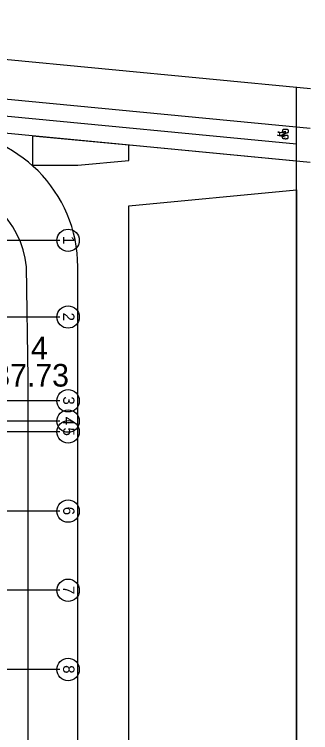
# Model space of a CAD drawing. Extents: x -264165 to -263575, y -1242333 to -1242036.
# Drawn here: x -263791.5 to -263765.3, y -1242131.5 to -1242068 of the extents above; entities that cross this region are included whole.
import ezdxf

# ---------------------------------------------------------------- set-up
doc = ezdxf.new("R2010")
doc.units = 0
for name, color, linetype in [('KFA_BODY_VYTYCOVAK', 7, 'Continuous'), ('KFA_HESCON_OSI_STAVBY', 7, 'Continuous'), ('KFA_SITUACIA_DRS_VYTYCOVAK_SEDA', 7, 'Continuous')]:
    doc.layers.add(name, color=color, linetype=linetype)

msp = doc.modelspace()

# ---------------------------------------------------------------- linework, layer by layer
at = {"layer": 'KFA_HESCON_OSI_STAVBY'}
for p, q in [((-263787.486, -1242087.957), (-263921.823, -1242087.957)), ((-263787.486, -1242087.957), (-263787.486, -1242087.957)), ((-263787.486, -1242094.732), (-263921.823, -1242094.732)), ((-263787.486, -1242094.732), (-263787.486, -1242094.732)), ((-263787.486, -1242102.132), (-263921.823, -1242102.132)), ((-263787.486, -1242102.132), (-263787.486, -1242102.132)), ((-263787.486, -1242103.932), (-263921.823, -1242103.932)), ((-263787.486, -1242103.932), (-263787.486, -1242103.932)), ((-263787.486, -1242104.882), (-263921.823, -1242104.882)), ((-263787.486, -1242104.882), (-263787.486, -1242104.882)), ((-263787.486, -1242111.882), (-263921.823, -1242111.882)), ((-263787.486, -1242111.882), (-263787.486, -1242111.882)), ((-263787.486, -1242118.882), (-263921.823, -1242118.882)), ((-263787.486, -1242118.882), (-263787.486, -1242118.882)), ((-263787.486, -1242125.882), (-263921.823, -1242125.882)), ((-263787.486, -1242125.882), (-263787.486, -1242125.882))]:
    msp.add_line(p, q, dxfattribs=at)
for centre in [(-263786.751, -1242087.956), (-263786.751, -1242094.731), (-263786.751, -1242102.131), (-263786.751, -1242103.931), (-263786.751, -1242104.881), (-263786.751, -1242111.881), (-263786.751, -1242118.881), (-263786.751, -1242125.881)]:
    msp.add_circle(centre, 0.991, dxfattribs=at)
at = {"layer": 'KFA_SITUACIA_DRS_VYTYCOVAK_SEDA'}
for p, q in [((-263765.318, -1242074.565), (-263863.949, -1242065.106)), ((-263765.364, -1242078.076), (-263864.283, -1242068.59)), ((-263766.58, -1242079.467), (-263864.426, -1242070.084)), ((-263765.366, -1242081.09), (-263864.57, -1242071.577)), ((-263766.58, -1242080.973), (-263864.546, -1242071.579)), ((-263766.58, -1242144.85), (-263766.58, -1242074.389)), ((-263768.17, -1242078.443), (-263768.167, -1242078.342)), ((-263768.037, -1242078.422), (-263768.168, -1242078.393)), ((-263768.046, -1242078.721), (-263768.037, -1242078.422)), ((-263768.037, -1242078.422), (-263767.545, -1242078.308)), ((-263767.552, -1242078.528), (-263768.037, -1242078.422)), ((-263767.811, -1242078.279), (-263767.812, -1242078.312)), ((-263767.812, -1242078.312), (-263767.812, -1242078.333)), ((-263767.812, -1242078.333), (-263767.811, -1242078.349)), ((-263767.809, -1242078.257), (-263767.811, -1242078.279)), ((-263767.811, -1242078.349), (-263767.808, -1242078.363)), ((-263767.806, -1242078.239), (-263767.809, -1242078.257)), ((-263767.808, -1242078.363), (-263767.803, -1242078.375)), ((-263767.801, -1242078.223), (-263767.806, -1242078.239)), ((-263767.803, -1242078.375), (-263767.796, -1242078.387)), ((-263767.795, -1242078.209), (-263767.801, -1242078.223)), ((-263767.796, -1242078.387), (-263767.787, -1242078.398)), ((-263767.786, -1242078.197), (-263767.795, -1242078.209)), ((-263767.787, -1242078.398), (-263767.775, -1242078.407)), ((-263767.776, -1242078.188), (-263767.786, -1242078.197)), ((-263767.763, -1242078.18), (-263767.776, -1242078.188)), ((-263767.775, -1242078.407), (-263767.761, -1242078.416)), ((-263767.748, -1242078.174), (-263767.763, -1242078.18)), ((-263767.761, -1242078.416), (-263767.744, -1242078.424)), ((-263767.73, -1242078.169), (-263767.748, -1242078.174)), ((-263767.744, -1242078.424), (-263767.724, -1242078.431)), ((-263767.709, -1242078.165), (-263767.73, -1242078.169)), ((-263767.724, -1242078.431), (-263767.702, -1242078.437)), ((-263767.685, -1242078.163), (-263767.709, -1242078.165)), ((-263767.702, -1242078.437), (-263767.676, -1242078.442)), ((-263767.658, -1242078.161), (-263767.685, -1242078.163)), ((-263767.676, -1242078.442), (-263767.648, -1242078.446)), ((-263767.626, -1242078.161), (-263767.658, -1242078.161)), ((-263767.648, -1242078.446), (-263767.617, -1242078.45)), ((-263767.538, -1242078.162), (-263767.626, -1242078.161)), ((-263767.552, -1242078.529), (-263767.545, -1242078.308)), ((-263767.45, -1242078.166), (-263767.538, -1242078.162)), ((-263767.418, -1242078.168), (-263767.45, -1242078.166)), ((-263767.391, -1242078.172), (-263767.418, -1242078.168)), ((-263767.416, -1242078.45), (-263767.391, -1242078.446)), ((-263767.367, -1242078.176), (-263767.391, -1242078.172)), ((-263767.391, -1242078.446), (-263767.368, -1242078.442)), ((-263767.368, -1242078.442), (-263767.348, -1242078.436)), ((-263767.346, -1242078.181), (-263767.367, -1242078.176)), ((-263767.348, -1242078.436), (-263767.33, -1242078.429)), ((-263767.328, -1242078.187), (-263767.346, -1242078.181)), ((-263767.33, -1242078.429), (-263767.316, -1242078.421)), ((-263767.314, -1242078.193), (-263767.328, -1242078.187)), ((-263767.316, -1242078.421), (-263767.304, -1242078.412)), ((-263767.302, -1242078.202), (-263767.314, -1242078.193)), ((-263767.304, -1242078.412), (-263767.294, -1242078.402)), ((-263767.292, -1242078.212), (-263767.302, -1242078.202)), ((-263767.294, -1242078.402), (-263767.286, -1242078.391)), ((-263767.284, -1242078.225), (-263767.292, -1242078.212)), ((-263767.286, -1242078.391), (-263767.28, -1242078.379)), ((-263767.279, -1242078.239), (-263767.284, -1242078.225)), ((-263767.28, -1242078.379), (-263767.276, -1242078.365)), ((-263767.275, -1242078.255), (-263767.279, -1242078.239)), ((-263767.276, -1242078.365), (-263767.274, -1242078.35)), ((-263767.273, -1242078.274), (-263767.275, -1242078.255)), ((-263767.274, -1242078.35), (-263767.273, -1242078.328)), ((-263767.272, -1242078.296), (-263767.273, -1242078.274)), ((-263767.273, -1242078.328), (-263767.272, -1242078.296)), ((-263789.893, -1242078.738), (-263789.893, -1242081.311)), ((-263781.371, -1242079.555), (-263789.893, -1242078.738)), ((-263781.371, -1242079.555), (-263789.893, -1242078.738)), ((-263789.893, -1242078.738), (-263789.893, -1242081.311)), ((-263768.214, -1242078.685), (-263768.212, -1242078.62)), ((-263767.559, -1242078.828), (-263768.214, -1242078.685)), ((-263767.971, -1242078.726), (-263768.043, -1242078.71)), ((-263767.552, -1242078.528), (-263767.974, -1242078.737)), ((-263767.828, -1242078.832), (-263767.829, -1242078.853)), ((-263767.829, -1242078.853), (-263767.827, -1242078.869)), ((-263767.827, -1242078.799), (-263767.828, -1242078.832)), ((-263767.825, -1242078.777), (-263767.827, -1242078.799)), ((-263767.827, -1242078.869), (-263767.824, -1242078.883)), ((-263767.822, -1242078.758), (-263767.825, -1242078.777)), ((-263767.824, -1242078.883), (-263767.82, -1242078.895)), ((-263767.817, -1242078.743), (-263767.822, -1242078.758)), ((-263767.82, -1242078.895), (-263767.813, -1242078.907)), ((-263767.811, -1242078.729), (-263767.817, -1242078.743)), ((-263767.813, -1242078.907), (-263767.803, -1242078.917)), ((-263767.803, -1242078.717), (-263767.811, -1242078.729)), ((-263767.792, -1242078.707), (-263767.803, -1242078.717)), ((-263767.803, -1242078.917), (-263767.791, -1242078.927)), ((-263767.779, -1242078.7), (-263767.792, -1242078.707)), ((-263767.791, -1242078.927), (-263767.777, -1242078.935)), ((-263767.765, -1242078.694), (-263767.779, -1242078.7)), ((-263767.777, -1242078.935), (-263767.76, -1242078.943)), ((-263767.747, -1242078.689), (-263767.765, -1242078.694)), ((-263767.76, -1242078.943), (-263767.74, -1242078.95)), ((-263767.726, -1242078.685), (-263767.747, -1242078.689)), ((-263767.74, -1242078.95), (-263767.718, -1242078.957)), ((-263767.701, -1242078.682), (-263767.726, -1242078.685)), ((-263767.718, -1242078.957), (-263767.693, -1242078.962)), ((-263767.674, -1242078.681), (-263767.701, -1242078.682)), ((-263767.693, -1242078.962), (-263767.665, -1242078.966)), ((-263767.642, -1242078.68), (-263767.674, -1242078.681)), ((-263767.665, -1242078.966), (-263767.634, -1242078.969)), ((-263767.554, -1242078.682), (-263767.642, -1242078.68)), ((-263767.634, -1242078.969), (-263767.6, -1242078.972)), ((-263767.617, -1242078.45), (-263767.583, -1242078.452)), ((-263767.6, -1242078.972), (-263767.563, -1242078.974)), ((-263767.583, -1242078.452), (-263767.547, -1242078.454)), ((-263767.563, -1242078.974), (-263767.526, -1242078.974)), ((-263767.466, -1242078.686), (-263767.554, -1242078.682)), ((-263767.547, -1242078.454), (-263767.51, -1242078.454)), ((-263767.526, -1242078.974), (-263767.492, -1242078.974)), ((-263767.51, -1242078.454), (-263767.476, -1242078.454)), ((-263767.492, -1242078.974), (-263767.461, -1242078.972)), ((-263767.476, -1242078.454), (-263767.445, -1242078.452)), ((-263767.434, -1242078.688), (-263767.466, -1242078.686)), ((-263767.461, -1242078.972), (-263767.433, -1242078.97)), ((-263767.445, -1242078.452), (-263767.416, -1242078.45)), ((-263767.407, -1242078.691), (-263767.434, -1242078.688)), ((-263767.433, -1242078.97), (-263767.407, -1242078.966)), ((-263767.383, -1242078.695), (-263767.407, -1242078.691)), ((-263767.407, -1242078.966), (-263767.384, -1242078.961)), ((-263767.384, -1242078.961), (-263767.364, -1242078.955)), ((-263767.362, -1242078.7), (-263767.383, -1242078.695)), ((-263767.364, -1242078.955), (-263767.347, -1242078.949)), ((-263767.345, -1242078.706), (-263767.362, -1242078.7)), ((-263767.347, -1242078.949), (-263767.332, -1242078.941)), ((-263767.33, -1242078.713), (-263767.345, -1242078.706)), ((-263767.332, -1242078.941), (-263767.32, -1242078.932)), ((-263767.318, -1242078.722), (-263767.33, -1242078.713)), ((-263767.32, -1242078.932), (-263767.31, -1242078.922)), ((-263767.308, -1242078.732), (-263767.318, -1242078.722)), ((-263767.31, -1242078.922), (-263767.302, -1242078.911)), ((-263767.301, -1242078.744), (-263767.308, -1242078.732)), ((-263767.302, -1242078.911), (-263767.296, -1242078.899)), ((-263767.295, -1242078.758), (-263767.301, -1242078.744)), ((-263767.296, -1242078.899), (-263767.293, -1242078.885)), ((-263767.291, -1242078.774), (-263767.295, -1242078.758)), ((-263767.293, -1242078.885), (-263767.29, -1242078.869)), ((-263767.289, -1242078.793), (-263767.291, -1242078.774)), ((-263767.29, -1242078.869), (-263767.289, -1242078.848)), ((-263767.289, -1242078.816), (-263767.289, -1242078.793)), ((-263767.289, -1242078.848), (-263767.289, -1242078.816)), ((-263781.371, -1242080.901), (-263781.371, -1242079.555)), ((-263781.371, -1242080.901), (-263781.371, -1242079.555)), ((-263785.893, -1242081.311), (-263781.371, -1242080.901)), ((-263785.893, -1242081.311), (-263781.371, -1242080.901)), ((-263766.58, -1242088.382), (-263766.58, -1242080.973)), ((-263789.893, -1242081.311), (-263785.893, -1242081.311)), ((-263789.893, -1242081.311), (-263785.893, -1242081.311)), ((-263781.371, -1242084.903), (-263766.58, -1242083.485)), ((-263781.371, -1242084.903), (-263766.58, -1242083.485)), ((-263766.58, -1242083.485), (-263766.58, -1242201.01)), ((-263766.58, -1242083.485), (-263766.58, -1242201.01)), ((-263781.364, -1242208.936), (-263781.371, -1242084.903)), ((-263781.364, -1242208.936), (-263781.371, -1242084.903)), ((-263766.58, -1242201.01), (-263766.58, -1242088.382)), ((-263790.279, -1242100.14), (-263790.432, -1242090.308)), ((-263785.893, -1242228.625), (-263785.893, -1242090.308)), ((-263790.279, -1242228.625), (-263790.279, -1242100.14))]:
    msp.add_line(p, q, dxfattribs=at)
for centre, radius, start, end in [((-263797.893, -1242090.308), 12, 0, 90), ((-263798.744, -1242091.156), 8.355, 5.82518, 87.59058)]:
    msp.add_arc(centre, radius, start, end, dxfattribs=at)

# ---------------------------------------------------------------- texts
at = {"layer": 'KFA_BODY_VYTYCOVAK'}
for s, p in [('4', (-263790.033, -1242098.476)), ('237.73', (-263794.852, -1242100.879))]:
    msp.add_text(s, height=2, dxfattribs=at).set_placement(p)
at = {"layer": 'KFA_HESCON_OSI_STAVBY'}
for s, p in [('1', (-263787.186, -1242087.568)), ('2', (-263787.186, -1242094.343)), ('3', (-263787.186, -1242101.743)), ('4', (-263787.186, -1242103.543)), ('5', (-263787.186, -1242104.493)), ('6', (-263787.186, -1242111.493)), ('7', (-263787.186, -1242118.493)), ('8', (-263787.186, -1242125.493))]:
    msp.add_text(s, height=1, rotation=270, dxfattribs=at).set_placement(p)

doc.saveas('drawing.dxf')
